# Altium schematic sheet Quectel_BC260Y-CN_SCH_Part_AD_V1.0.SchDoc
size A1
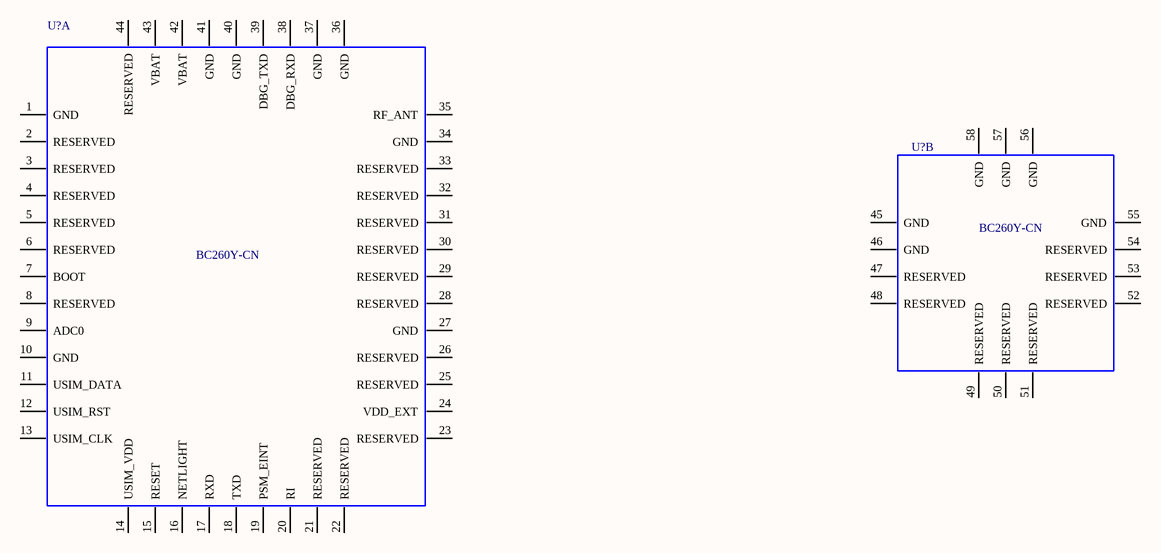
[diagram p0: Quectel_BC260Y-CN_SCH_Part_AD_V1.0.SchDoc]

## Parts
(Parts that share a designator on the sheet are numbered #1, #2 ... from top to bottom, then left to right.)
U?#1  BC260Y-CN  (part B of 2)
U?#2  BC260Y-CN  (part A of 2)

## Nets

Not connected (* = marked no-connect by the designer): U?#1 45(GND) 46(GND) 47(RESERVED) 48(RESERVED) 49(RESERVED) 50(RESERVED) 51(RESERVED) 52(RESERVED) 53(RESERVED) 54(RESERVED) 55(GND) 56(GND) 57(GND) 58(GND); U?#2 1(GND) 2(RESERVED) 3(RESERVED) 4(RESERVED) 5(RESERVED) 6(RESERVED) 7(BOOT) 8(RESERVED) 9(ADC0) 10(GND) 11(USIM_DATA) 12(USIM_RST) 13(USIM_CLK) 14(USIM_VDD) 15(RESET) 16(NETLIGHT) 17(RXD) 18(TXD) 19(PSM_EINT) 20(RI) 21(RESERVED) 22(RESERVED) 23(RESERVED) 24(VDD_EXT) 25(RESERVED) 26(RESERVED) 27(GND) 28(RESERVED) 29(RESERVED) 30(RESERVED) 31(RESERVED) 32(RESERVED) 33(RESERVED) 34(GND) 35(RF_ANT) 36(GND) 37(GND) 38(DBG_RXD) 39(DBG_TXD) 40(GND) 41(GND) 42(VBAT) 43(VBAT) 44(RESERVED)

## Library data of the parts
U?#1 U?#2 = BC260Y-CN: Part Description: BC260Y-CN 17.7×15.8mm H2.2mm RO; Manufacturer: QUECTEL; Geometry.Height: 2.2mm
